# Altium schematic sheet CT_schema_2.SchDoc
size 276 x 169 mm
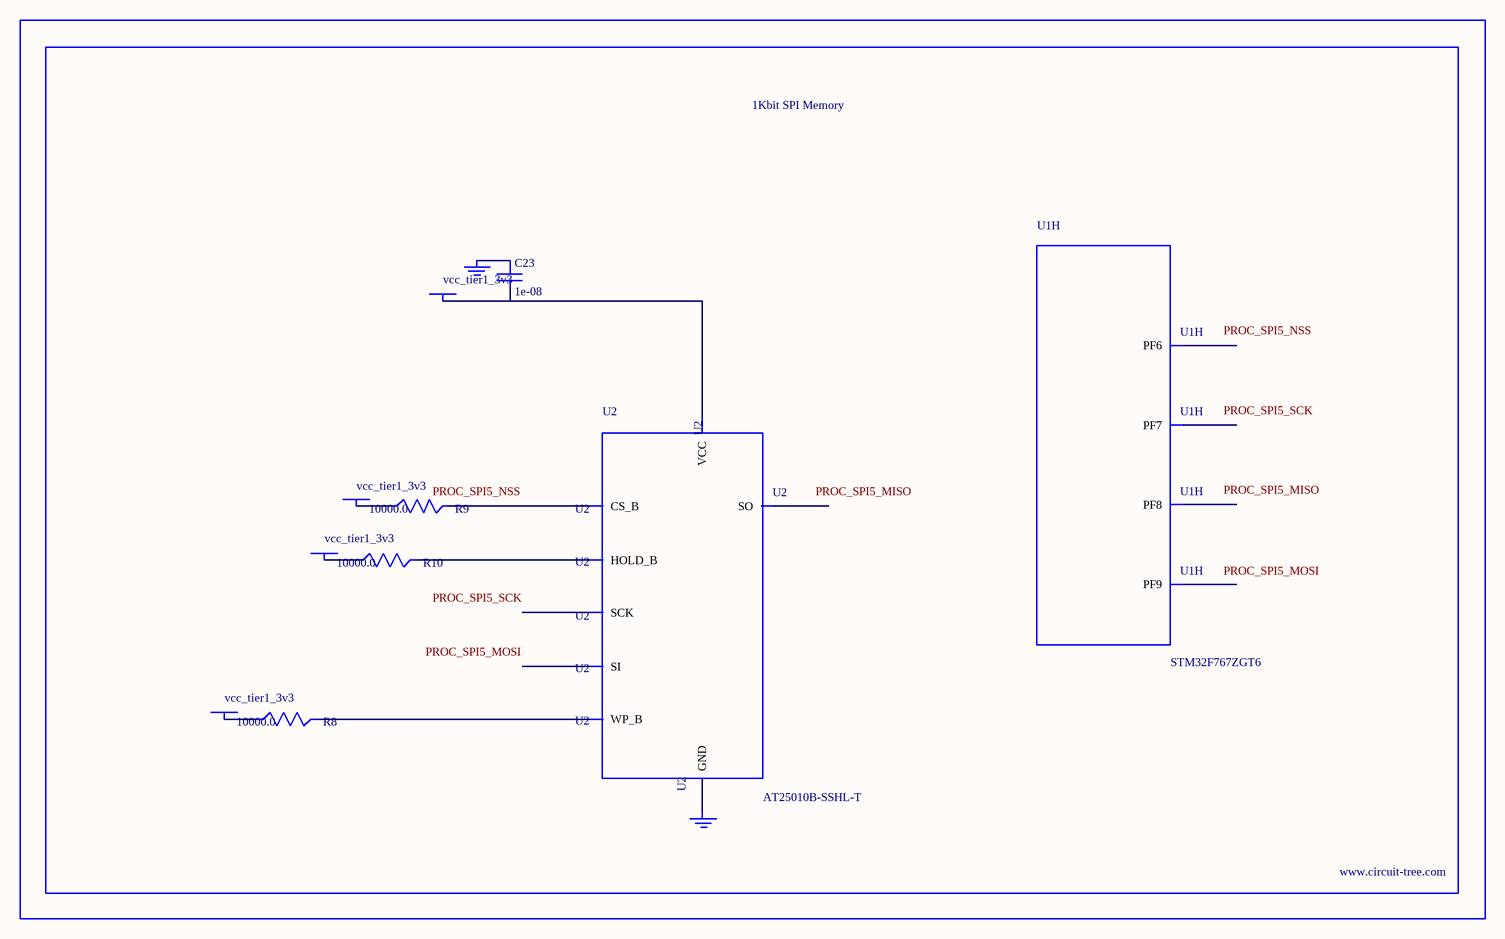
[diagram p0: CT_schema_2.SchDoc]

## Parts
BORDER1  (no value)
C23  1e-08  [C0402]
GND_INSTANCE_1_0  (no value)
GND_INSTANCE_1_1  (no value)
POWER_INSTANCE_1_0  vcc_tier1_3v3
POWER_INSTANCE_1_1  vcc_tier1_3v3
POWER_INSTANCE_1_2  vcc_tier1_3v3
POWER_INSTANCE_1_3  vcc_tier1_3v3
R8  10000.0  [R0603]
R9  10000.0  [R0603]
R10  10000.0  [R0603]
U1  STM32F767ZGT6  [LQFP144]  (part H of 13)
U2  AT25010B-SSHL-T  [SOIC-8]

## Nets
NetC23_1: C23.1 GND_INSTANCE_1_0.0(GND)
NetC23_2: C23.2 POWER_INSTANCE_1_3.0(PWR) U2.8(VCC)
NetGND_INSTANCE_1_1_0: GND_INSTANCE_1_1.0(GND) U2.4(GND)
NetPOWER_INSTANCE_1_0_0: POWER_INSTANCE_1_0.0(PWR) R9.1
NetPOWER_INSTANCE_1_1_0: POWER_INSTANCE_1_1.0(PWR) R8.1
NetPOWER_INSTANCE_1_2_0: POWER_INSTANCE_1_2.0(PWR) R10.1
NetR8_2: R8.2 U2.3(WP_B)
NetR9_2: R9.2 U2.1(CS_B)
NetR10_2: R10.2 U2.7(HOLD_B)

Not connected (* = marked no-connect by the designer): U1 18(PF6) 19(PF7) 20(PF8) 21(PF9); U2 2(SO) 5(SI) 6(SCK)

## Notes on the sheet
- Labels drawn without touching a wire or pin: PROC_SPI5_MISO, PROC_SPI5_MOSI, PROC_SPI5_NSS, PROC_SPI5_SCK

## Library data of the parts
BORDER1 = BORDER_PAGE1
C23 = C0402C103K3RAC
GND_INSTANCE_1_0 GND_INSTANCE_1_1 = GND
POWER_INSTANCE_1_0-POWER_INSTANCE_1_3 = PWR
R8-R10 = RC0603JR-0710KL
